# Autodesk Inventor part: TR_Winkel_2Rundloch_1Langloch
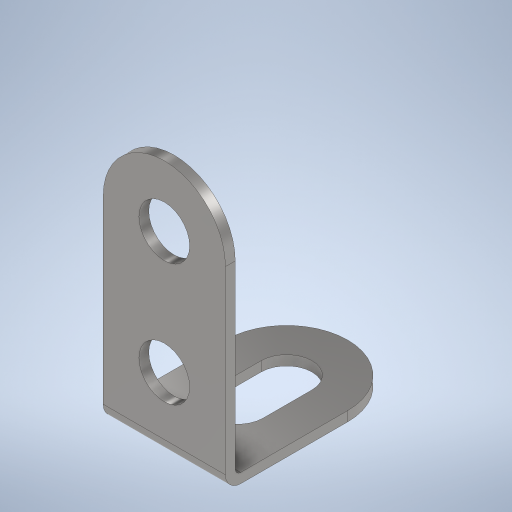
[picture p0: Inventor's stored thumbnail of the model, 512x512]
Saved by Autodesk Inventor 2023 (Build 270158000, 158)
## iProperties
Created: 2023-11
Part Number: TR_Winkel_2Rundloch_1Langloch
Material: Edelstahl
Document SubType Name: Modeling
Designer: Administrator
Density: 8 g/cm^3
Appearance: Halbpoliert
Author: Administrator
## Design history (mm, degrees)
sketch "Skizze1"
  geometry: L1 (1.25, 0)-(21, 0); L2 (21, 0)-(21, -0.8); L3 (21, -0.8)-(1.25, -0.8); L4 (0.8, -1.25)-(0.8, -15); L5 (0.8, -15)-(0, -15); L6 (0, -15)-(0, -1.25); A1 r 1.25 centre (1.25, -1.25) between (1.25, 0) and (0, -1.25); A2 r 0.45 centre (1.25, -1.25) between (1.25, -0.8) and (0.8, -1.25); 1 further point
  constraints: 12 end point, 5 perpendicular, 4 point on circle, 4 tangent, 2 centre point, 2 point on line, 1 coincident, 1 horizontal
  dimensions: "d0" = 1.25 radius of A1; "d2" = 0.8 distance between parallel lines of L3 L1 (= Dicke); "d3" = 21 distance of point (0, 0) L1.end; "d4" = 15 distance of point (0, 0) L5.end
extrude "Extrusion1" new body sketch "Skizze1" stored distance "d5" = 10 (= Einheitsmaß); taper "d6" = 0 deg
fillet "Rundung1" dims "d7" = 5 (= 0.5 x Einheitsmaß)
sketch "Skizze2"
  geometry: L1 (5, 8.75)-(5, 4.75); L2 (2.925, 8.75)-(2.925, 4.75); L3 (7.075, 4.75)-(7.075, 8.75); L4 (10, -1.25)-(0, -1.25) reference; A1 r 2.075 centre (5, 8.75) between (7.075, 8.75) and (2.925, 8.75); A2 r 2.075 centre (5, 4.75) between (2.925, 4.75) and (7.075, 4.75); 4 further points
  constraints: 8 end point, 4 point on circle, 4 tangent, 2 centre point, 1 horizontal alignment, 1 midpoint, 1 parallel, 1 vertical, 1 vertical alignment
  dimensions: "d9" = 4.15 diameter of A2 (= 2 x Radius); "d10" = 4 distance of L1.start L1.end
extrude "Extrusion2" cut sketch "Skizze2" extent not by distance; stored distance "d11" = 0; taper "d12" = 0 deg
sketch "Skizze3"
  geometry: C1 r 2.075 at (5, 14.75); A1 r 5 centre (5, 14.75) between (10, 14.75) and (0, 14.75) reference; 1 further point
  constraints: 1 centre point, 1 coincident
  dimensions: "d13" = 4.15 diameter of C1 (= 2 x Radius)
extrude "Extrusion3" cut sketch "Skizze3" extent not by distance; stored distance "d14" = 0; taper "d15" = 0 deg
pattern_linear "Rechteckige Anordnung1" dims "d18" = 10 (= Einheitsmaß)
node "Volumenkörper1"
other parameters: "Einheitsmaß" = 10 [user parameter; used in 3 equation terms], "Radius" = 2.075 [user parameter; used in 2 equation terms], "Fasen" = 0.5 [user parameter], "Dicke" = 0.8 [user parameter; used in 1 equation term], "Breitloch" = 2 [user parameter], "Langloch" = 32 [user parameter], "AchteckUmkreis" = 6 [user parameter], "DAchsAufnahme" = 4.1 [user parameter], "AchsDurchmesser" = 4 [user parameter], "AchsFase" = 0.5 [user parameter]
